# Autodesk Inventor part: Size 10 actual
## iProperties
Created: 2006-11
Part Number: Size 10 actual
Document SubType Name: Modeling
Designer: Andrew DuBuc
Density: 1 g/cm^3
Author: Andrew DuBuc
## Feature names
1. Revolution1
